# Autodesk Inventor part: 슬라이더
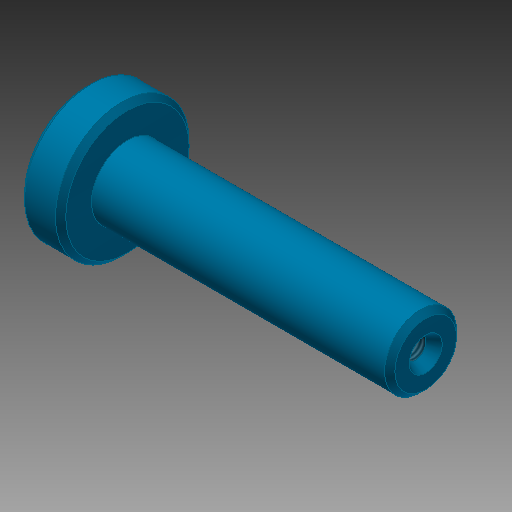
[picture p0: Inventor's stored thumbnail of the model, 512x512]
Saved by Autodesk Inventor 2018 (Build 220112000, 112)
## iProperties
Created: 2019-01
Part Number: 슬라이더
Material: 강철, 연강
Document SubType Name: Modeling
Designer: mduedu
Density: 7.86 g/cm^3
Appearance: 하늘색 중간
Mass: 101.006 g
Surface Area: 43.3118 cm^2
Volume: 12.8506 cm^3
Author: mduedu
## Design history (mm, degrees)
sketch "스케치1"
  geometry: L1 (0, 0)-(8, 0); L2 (8, 0)-(8, 13); L3 (8, 13)-(0, 13); L4 (0, 13)-(0, 0); L5 (8, 0)-(66, 0); L6 (66, 0)-(66, 7); L7 (66, 7)-(8, 7); L8 (8, 7)-(8, 0)
  constraints: 16 end point, 4 parallel, 2 horizontal, 2 perpendicular
  dimensions: "d0" = 66 distance between parallel lines of L6 L4; "d2" = 8 distance of L2.end L3.end; "d3" = 26 diameter of L3 L1; "d4" = 14 diameter of L7 L5
revolve "회전1" sketch "스케치1" stored, may be unused: angle "d5" = 90 deg
chamfer "모따기1" distance "d6" = 1; stored, may be unused: second distance "d7" = 2, angle "d8" = 45 deg
hole "구멍1" diameter "d14" = 4.134; stored, may be unused: countersink angle "d18" = 60 deg, drill point angle "d20" = 118 deg; dims "d15" = 12, "d16" = 6.3, "d17" = 2, "d19" = 15, "d26" = 10, "d27" = 10
chamfer "모따기4" distance "d24" = 1; stored, may be unused: second distance "d25" = 2, angle "d28" = 30 deg
sketch "스케치2"
  geometry: L1 (66, 2.067)-(66, -2.067) reference; L2 (66, 0)-(64, 0); L3 (64, 0)-(64, 2.067); L4 (66, 3.222)-(66, 0); L5 (66, 3.222)-(64, 2.067); L6 (51, 2.067)-(66, 2.067) reference; 1 further point
  constraints: 8 end point, 1 horizontal, 1 midpoint, 1 parallel, 1 perpendicular, 1 point on line
  dimensions: "d29" = 2 horizontal distance of L4.start L3.end; "d31" = 30 deg angle of L2 L5
revolve "회전2" sketch "스케치2" stored, may be unused: angle "d33" = 90 deg
node "솔리드1"
